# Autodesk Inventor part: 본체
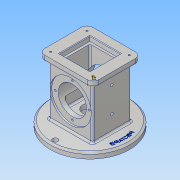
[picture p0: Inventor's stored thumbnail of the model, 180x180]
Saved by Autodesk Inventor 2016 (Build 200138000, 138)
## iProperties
Created: 2019-08
Part Number: 본체
Material: 알루미늄 6061
Document SubType Name: Modeling
Designer: 605-15
Mass: 1038.83 g
Surface Area: 783.574 cm^2
Volume: 384.751 cm^3
Density: 2.7 g/cm^3
Appearance: 알루미늄 - 평지
Author: 605-15
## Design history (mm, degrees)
sketch "스케치1" dims "d3" = 118
  geometry: L1 (37, -33)-(-37, -33); L2 (-37, -33)-(-37, 33); L3 (-37, 33)-(37, 33); L4 (37, 33)-(37, -33); L5 (37, -33)-(-37, 33); L6 (-37, -33)-(37, 33); C1 r 67.5 at (0, 0); 7 further points
  constraints: 12 end point, 3 midpoint, 2 coincident, 2 parallel, 2 vertical alignment, 1 centre point, 1 horizontal, 1 perpendicular, 7 other
  dimensions: "d0" = 135 diameter of C1; "d1" = 74 distance of L2.end L3.end; "d2" = 66 distance of L1.end L2.end; "d6" = 360 deg dimension on point (0, 0) point (0, -59) (derived)
extrude "돌출1" new body sketch "스케치1" distance "d8" = 10; taper "d9" = 0 deg
extrude "돌출2" join sketch "스케치1" distance "d10" = 108; taper "d11" = 0 deg
sketch "스케치2"
  geometry: L1 (37, 33)-(-37, 33) reference; L2 (-37, 33)-(-37, -33) reference; L3 (-37, -33)-(37, -33) reference; L4 (37, -33)-(37, 33) reference; L5 (-36, -41)-(36, -41); L6 (46, -31)-(46, 31); L7 (36, 41)-(-36, 41); L8 (-46, 31)-(-46, -31); L9 (-46, -41)-(46, 41); L10 (46, -41)-(-46, 41); A1 r 10 centre (-36, 31) between (-36, 41) and (-46, 31); A2 r 10 centre (-36, -31) between (-46, -31) and (-36, -41); A3 r 10 centre (36, -31) between (36, -41) and (46, -31); A4 r 10 centre (36, 31) between (46, 31) and (36, 41); 1 further point
  constraints: 12 end point, 8 point on circle, 8 point on line, 8 tangent, 4 centre point, 3 equal radius, 2 midpoint, 2 parallel, 1 horizontal, 1 perpendicular
  dimensions: "d12" = 92 distance of L10.end L9.end; "d13" = 82 distance of L9.end L10.start; "d14" = 10 radius of A1
extrude "돌출3" join sketch "스케치2" distance "d15" = 10; taper "d16" = 0 deg
sketch "스케치3"
  geometry: L1 (-26, -26)-(26, -26); L2 (26, -26)-(26, 26); L3 (26, 26)-(-26, 26); L4 (-26, 26)-(-26, -26); L5 (-26, -26)-(26, 26); L6 (26, -26)-(-26, 26); L7 (-22, 22)-(22, 22); L8 (22, 22)-(22, -22); L9 (22, -22)-(-22, -22); L10 (-22, -22)-(-22, 22); L11 (-22, 22)-(22, -22); L12 (22, 22)-(-22, -22); 1 further point
  constraints: 24 end point, 4 midpoint, 4 parallel, 2 horizontal, 2 perpendicular
  dimensions: "d17" = 52 distance of L3.end L2.end; "d18" = 52 distance of L2.end L1.end; "d19" = 44 distance of L8.end L9.end; "d20" = 44 distance of L7.end L8.end
extrude "돌출4" cut sketch "스케치3" distance "d21" = 8; taper "d22" = 0 deg
extrude "돌출5" cut sketch "스케치3" distance "d23" = 82; taper "d24" = 0 deg
sketch "스케치4"
  geometry: C1 r 67.5 at (0, 0) reference; C2 r 25 at (0, 0); C3 r 12.5 at (0, 0)
  constraints: 2 centre point, 2 coincident
  dimensions: "d25" = 50 diameter of C2; "d26" = 25 diameter of C3
extrude "돌출6" cut sketch "스케치4" distance "d27" = 18; taper "d28" = 0 deg
extrude "돌출7" cut sketch "스케치4" stored distance "d29" = 0; taper "d30" = 0 deg
hole "구멍1" sketch "스케치1" diameter "d31" = 9; stored, may be unused: countersink angle "d35" = 90 deg, drill point angle "d37" = 118 deg; dims "d32" = 6, "d33" = 4, "d34" = 2, "d36" = 8
sketch "스케치5"
  geometry: L1 (-30.5, -10)-(104.5, -10) reference; C1 r 35 at (37, 44); 1 further point
  constraints: 1 centre point
  dimensions: "d38" = 70 diameter of C1; "d39" = 54 distance from line of C1.centre L1
extrude "돌출8" cut sketch "스케치5" distance "d40" = 3; taper "d41" = 0 deg
sketch "스케치6" dims "d42" = 58
  geometry: C1 r 35 at (0, 0) reference; C2 r 24 at (0, 0); 6 further points
  constraints: 2 coincident, 2 vertical alignment, 1 centre point, 7 other
  dimensions: "d43" = 48 diameter of C2; "d46" = 360 deg dimension on point (0, 0) point (0, 29) (derived)
extrude "돌출9" cut sketch "스케치6" stored distance "d48" = 3; taper "d49" = 0 deg
hole "구멍2" sketch "스케치6" diameter "d50" = 3.242; stored, may be unused: countersink angle "d54" = 90 deg, drill point angle "d56" = 118 deg; dims "d51" = 4, "d52" = 4, "d53" = 2, "d55" = 6
hole "구멍3" diameter "d59" = 3.242; stored, may be unused: countersink angle "d63" = 90 deg, drill point angle "d65" = 118 deg; dims "d57" = 10, "d58" = 10, "d60" = 4, "d61" = 4, "d62" = 2, "d64" = 6
chamfer "모따기1" distance "d72" = 1; stored, may be unused: second distance "d73" = 2, angle "d74" = 45 deg
fillet "모깎기1" dims "d75" = 3
fillet "모깎기2" dims "d76" = 3
fillet "모깎기3" dims "d77" = 3
chamfer "모따기2" distance "d78" = 3; stored, may be unused: second distance "d79" = 2, angle "d80" = 45 deg
sketch "스케치7"
  geometry: L1 (-37.5, -13)-(97.5, -13) reference; 3 further points
  constraints: 2 vertical alignment
  dimensions: "d81" = 37 distance from line of point (30, 24) L1; "d82" = 43 distance of point (30, 67) point (30, 24)
hole "구멍4" sketch "스케치7" at (30, 24), (30, 67) diameter "d83" = 4.917; stored, may be unused: countersink angle "d87" = 90 deg, drill point angle "d89" = 118 deg; dims "d84" = 15, "d85" = 4, "d86" = 2, "d88" = 15
sketch "스케치8"
  geometry: C1 r 64.5 at (0, 0) reference; C2 r 59 at (0, 0)
  constraints: 1 centre point, 1 coincident, 1 other
  dimensions: "d90" = 118 diameter of C2
feature "엠보싱1" sketch "스케치8" dims "d91" = 0.5, "d92" = 0
node "솔리드1"
mirror "대칭1"
pattern_linear "직사각형 패턴1" dims "d68" = 72, "d71" = 62
